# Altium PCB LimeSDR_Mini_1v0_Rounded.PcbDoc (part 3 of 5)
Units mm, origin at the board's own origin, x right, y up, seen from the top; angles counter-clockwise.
Board outline 69.3 x 52.3 mm, 8 copper layers (Top, L2, L3, L4, L5, L6, L7, Bottom), stack 1.555 mm thick; 371 components, 281 nets, 1644 pads, 778 vias.
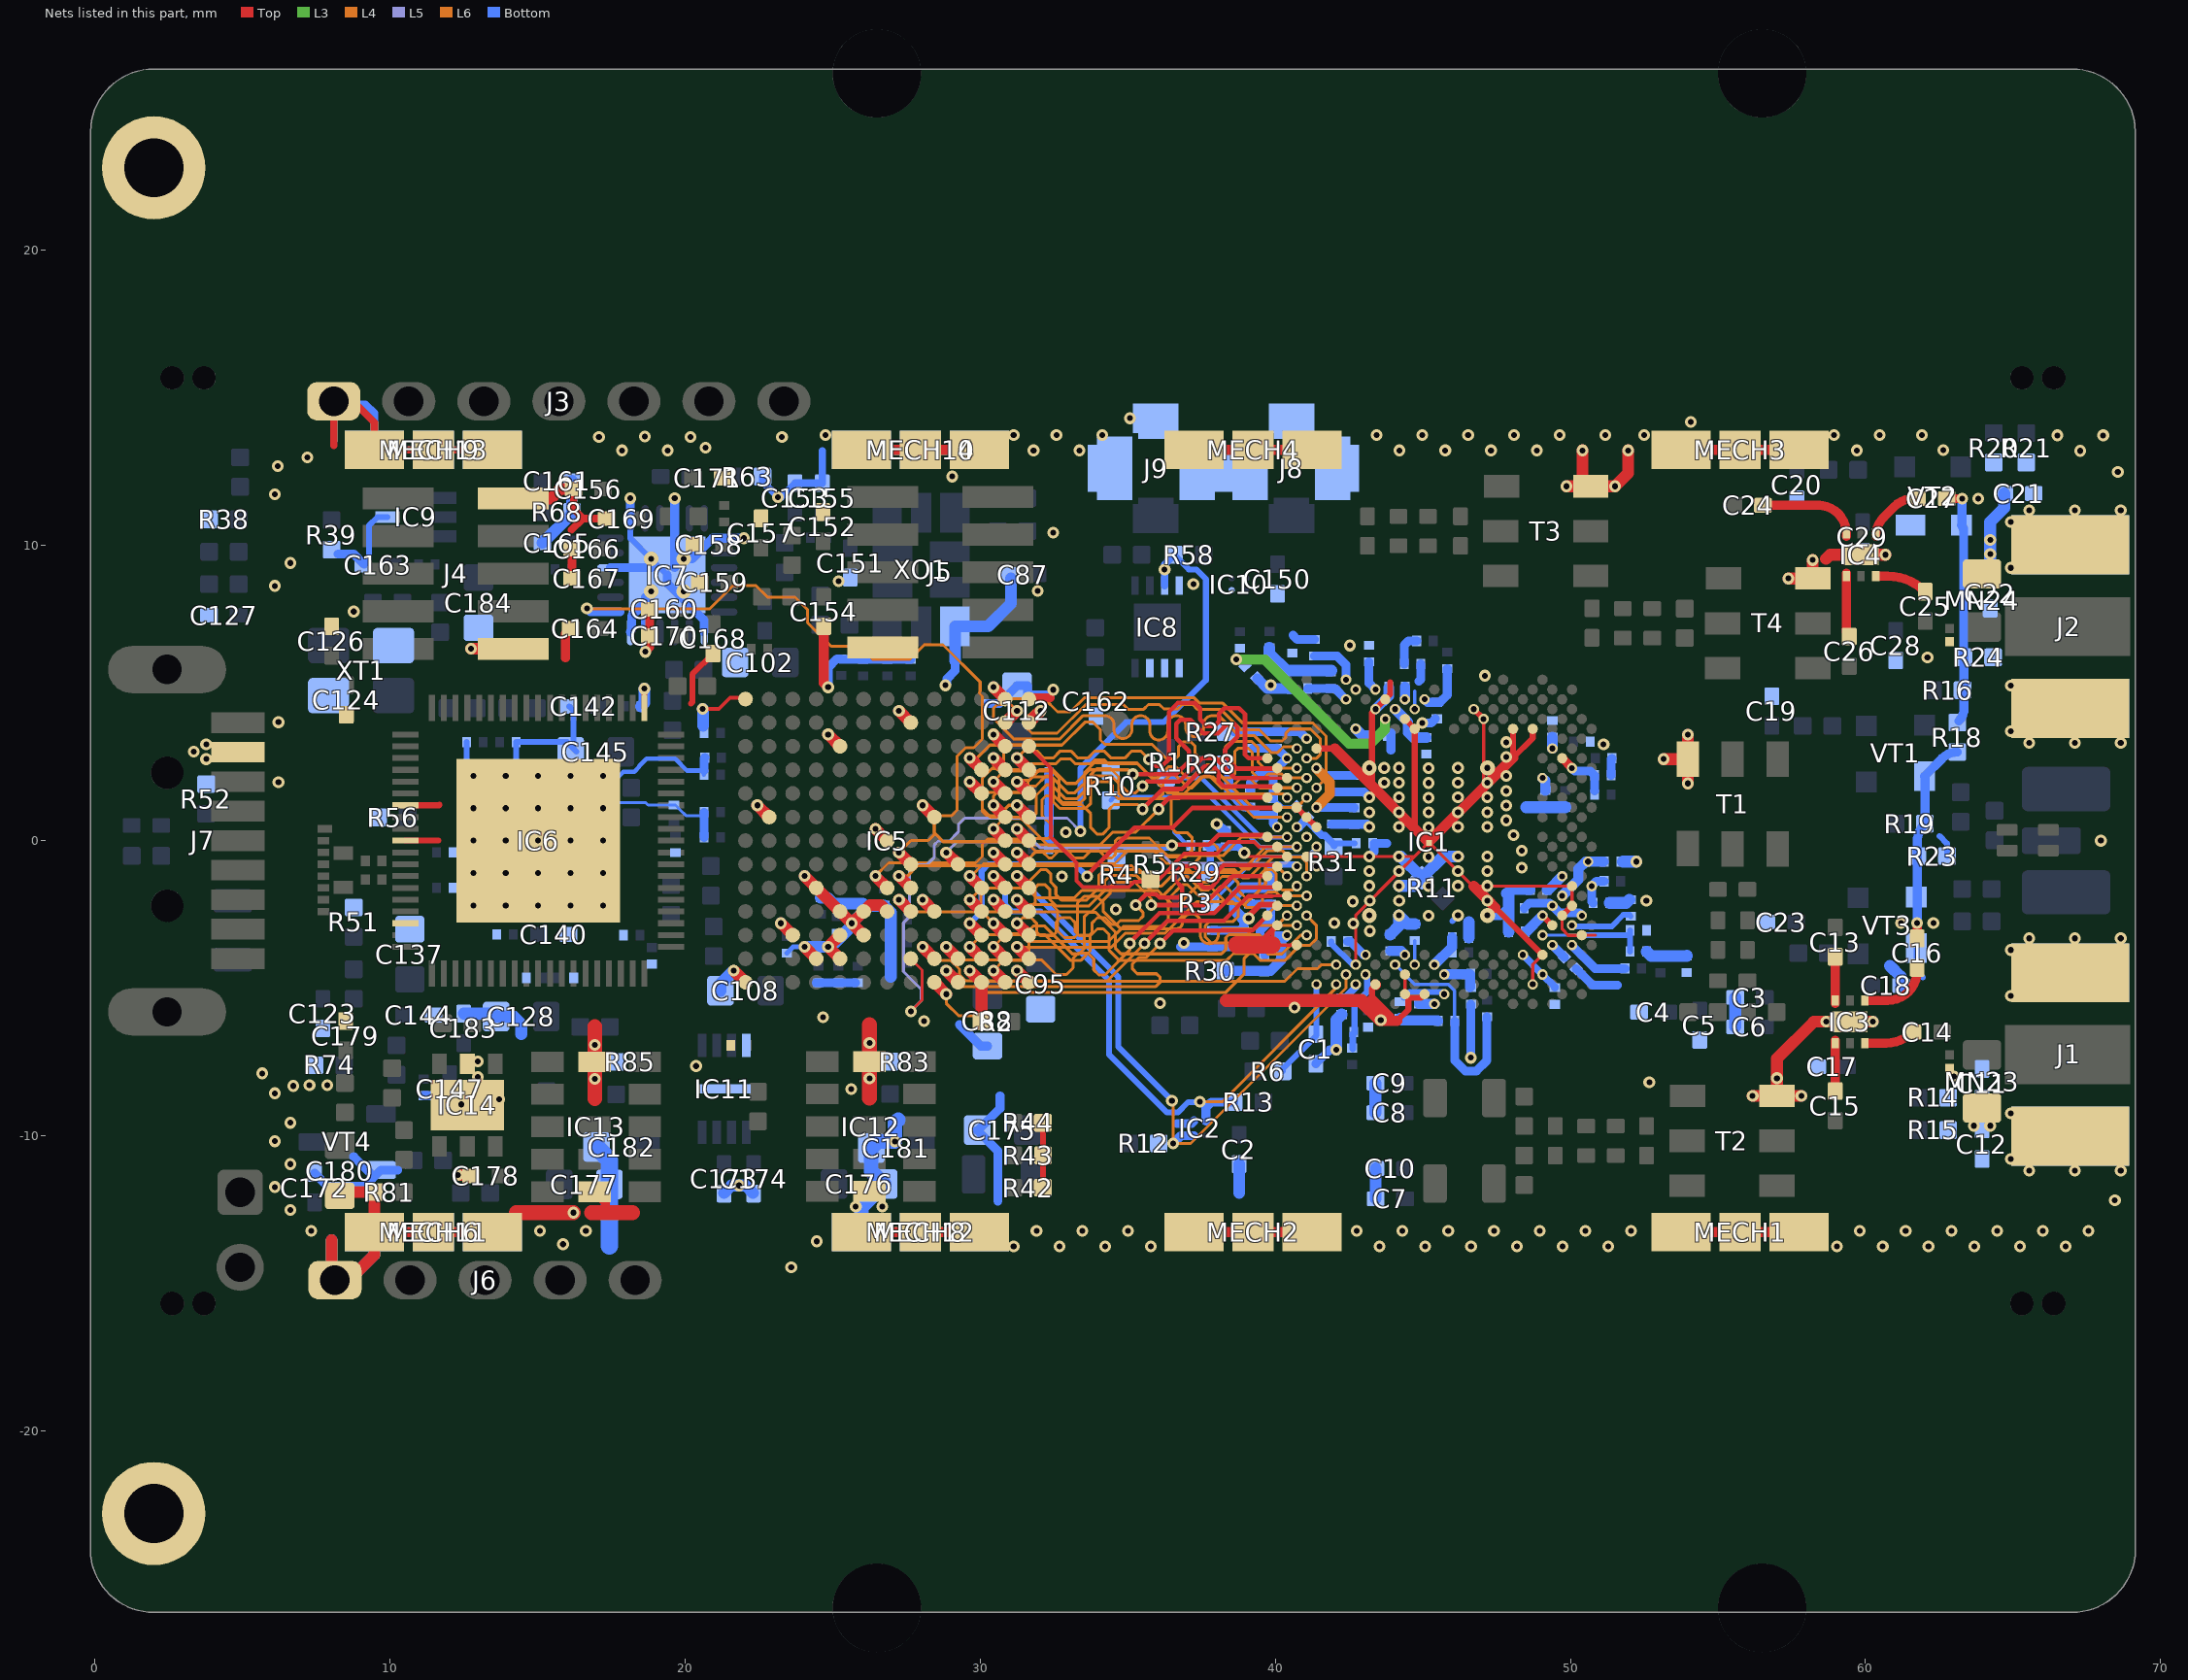
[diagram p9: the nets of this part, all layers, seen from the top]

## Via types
v1: diameter 0.4, hole 0.2, Top to Bottom, tented both sides, 544 vias
v2: diameter 0.4, hole 0.2, Top to Bottom, tented top, 113 vias
v3: diameter 0.35, hole 0.2, Top to Bottom, tented top, 87 vias
v4: diameter 0.5, hole 0.2, Top to Bottom, 25 vias
v5: diameter 0.5, hole 0.2, Top to Bottom, tented both sides, 8 vias
v6: diameter 0.35, hole 0.2, Top to Bottom, tented both sides, 1 vias

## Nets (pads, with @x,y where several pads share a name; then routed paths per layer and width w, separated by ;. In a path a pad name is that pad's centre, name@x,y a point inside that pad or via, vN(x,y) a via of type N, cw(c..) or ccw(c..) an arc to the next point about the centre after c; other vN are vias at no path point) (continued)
GND: C1.2 C2.2 C3.2 C4.1 C5.2 C6.1 C7.2 C8.2 C9.1 C10.1 C11.1 C12.2 C17.1 C18.1 C19.2 C20.2 C21.1 C22.2 C23.2 C28.1 C29.1 C30.2 C31.2 C32.2 C33.2 C34.2 C35.2 C36.2 C37.2 C38.2 C39.2 C40.2 C41.2 C42.2 C43.2 C44.2 C45.2 C46.2 C47.2 C48.2 C49.2 C50.2 C51.2 C52.2 C53.2 C54.2 C55.2 C56.2 C57.2 C58.1 C59.2 C60.2 C61.2 C62.2 C63.2 C64.2 C65.2 C66.2 C67.2 C68.2 C69.2 C70.1 C71.2 C72.2 C73.2 C74.2 C75.2 C76.2 C77.1 C78.2 C79.1 C80.2 C81.2 C82.2 C83.2 C84.2 C85.2 C86.2 C87.1 C88.1 C89.2 C90.2 C91.2 C92.2 C93.2 C94.2 C95.1 C96.2 C97.2 C98.2 C99.2 C100.2 C101.2 C102.1 C103.2 C104.2 C105.2 C106.2 C107.2 C108.1 C109.2 C110.2 C111.2 C112.1 C113.2 C114.2 C115.2 C116.2 C117.2 C118.2 C119.2 C120.2 C123.2 C124.2 C126.2 C127.2 C128.1 C129.1 C130.2 C131.1 C132.2 C133.1 C134.2 C135.1 C136.2 C137.1 C138.1 C139.2 C140.2 C141.2 C142.2 C143.2 C144.2 C145.1 C146.1 C147.2 C150.2 C151.1 C152.1 C153.1 C154.1 C155.1 C156.1 C157.1 C158.1 C159.1 C160.1 C161.1 C162.2 C163.2 C164.1 C165.1 C166.1 C167.1 C168.1 C169.1 C170.1 C171.1 C172.2 C173.1 C174.2 C175.1 C176.1 C177.1 C178.1 C179.1 C180.1 C181.1 C182.1 C183.1 C184.1 ESD1.2 ESD2.2 IC1.AA31 IC1.AF32 IC1.AG29 IC1.AJ7 IC1.AJ9 IC1.AJ19 IC1.AK12 IC1.AK20 IC1.AL13 IC1.AL23 IC1.AM22 IC1.AN25 IC1.B18 IC1.B20 IC1.C7 IC1.C23 IC1.D20 IC1.E25 IC1.F6 IC1.G31 IC1.GND IC1.H2 IC1.J33 IC1.K4 IC1.L3 IC1.N3 IC1.T30 IC1.V30 IC1.W29 IC1.Y30 IC2.B2 IC3.PAD IC4.PAD IC5.A1 IC5.A13 IC5.B8 IC5.C3 IC5.D2 IC5.D5 IC5.E2 IC5.E3 IC5.E4 IC5.E11 IC5.F3 IC5.F4 IC5.G4 IC5.G7 IC5.H12 IC5.J4 IC5.L9 IC5.M6 IC5.N1 IC5.N13 IC6.1 IC6.26 IC6.29 IC6.36 IC6.77 IC7.1 IC7.7 IC7.11 IC7.12 IC7.16 IC7.19 IC7.22 IC7.25 IC8.4 IC8.5 IC8.6 IC8.7 IC9.5 IC10.B2 IC11.4 IC11.PAD IC12.6 IC12.12 IC13.6 IC13.12 IC14.2 IC14.PAD J1.2 J2.2 J3.1 J4.2 J4.10 J5.9 J6.1 J7.4 J8.2 J9.2 MECH1.1 MECH2.1 MECH3.1 MECH4.1 MECH6.1 MECH8.1 MECH9.1 MECH10.1 MECH11.1 MECH12.1 MECH13.1 MECH14.1 NT1.2 pad.2 R10.2 R11.2 R23.1 R24.1 R38.1 R39.2 R42.1 R43.1 R44.1 R51.1 R52.1 R56.1 R63.1 R68.2 R74.1 R81.2 R83.1 R85.1 T1.3 T2.3 T3.3 T4.3 VT2.1 VT3.1 VT4.S XO1.4 XT1.2 XT1.4 | length 317.2
  Top w0.11: 39.926,-3.009 39.926,-3.283 40.179,-3.536 IC1.G31@40.731,-3.536 ; IC1.T30@41.064,-0.539 44.711,-0.539 ; v3(42.729,-4.202) 42.729,-2.521 44.204,-1.046 44.711,-0.539 ; IC1.B20@44.394,-5.201 IC1.D20@44.394,-4.535 ; 47.058,1.808 v3(47.058,4.123) ; v3(48.723,-4.868) 48.723,-4.202 IC1.F6@49.056,-3.869 ; IC1.K4@49.722,-2.537 49.722,-3.004 49.924,-3.206 50.385,-3.206 IC1.H2@50.388,-3.203 50.849,-3.203 ; IC1.L3@50.052,-2.204 IC1.N3@50.052,-1.638 ; IC1.N3@50.055,-1.538 46.725,-1.538 46.68,-1.538 45.196,-0.054 44.711,-0.539
  Top w0.12: v1(20.6,4.465) 21.15,4.465 21.528,4.843 IC5.A13@22.007,4.843
  Top w0.2: IC6.29@10.525,0 11.64,0 ; IC6.26@10.525,1.2 11.66,1.2 11.675,1.215 ; IC6.1@18.625,4.5 v1(18.625,5.15) ; 20.2,4.64 20.25,4.69 20.25,5.64 C168.1@20.95,6.34 ; R42.1@32.125,-11.76 R44.1@32.125,-9.56 ; 39.476,-3.459 39.926,-3.009 IC1.J33@40.065,-2.87 ; IC1.AA31@40.731,1.126 IC1.Y30@41.064,0.793 IC1.W29@41.397,0.46 ; IC1.AG29@41.397,3.124 42.018,3.124 ; 43.278,-5.387 43.278,-5.015 IC1.C23@43.41,-4.883 ; 43.278,1.864 43.278,4.339 v3(43.395,4.456) IC1.AM22@43.845,4.906 ; IC1.AM22@43.728,4.789 43.9,4.961 43.9,5.365 ; 44.124,-6.107 44.511,-5.72 IC1.B20@44.511,-5.318 ; IC1.B20@44.394,-5.201 IC1.B20@44.511,-5.318 ; IC1.AK20@44.394,4.123 IC1.AJ19@44.727,3.79 44.727,0.415 ; IC1.B18@45.06,-5.201 44.943,-5.318 IC1.B20@44.511,-5.318 ; v3(46.725,4.456) v3(47.058,4.123) ; 47.456,-2.269 IC1.F6@49.056,-3.869 ; IC1.AJ9@48.057,3.79 48.057,2.807 48.723,3.473 IC1.AJ7@48.723,3.79 ; IC1.K4@49.722,-2.537 IC1.L3@50.055,-2.204
  Top w0.25: 8.096,13.386 8.096,14.79 8.85,14.79 9.475,14.165 MECH9.1@9.475,13.24 MECH9.1@11.475,13.24 MECH9.1@13.475,13.24 ; 16.15,10.525 16.54,10.915 ; C156.1@16.225,11.915 16.225,11.23 16.54,10.915 ; C169.1@17.35,10.915 16.54,10.915
  Top w0.3: 15.95,6.19 15.95,7.015 C164.1@16.125,7.19 ; C167.1@16.175,8.89 C166.1@16.175,9.715 ; IC13.6@16.939,-11.895 17.3,-12.256 17.3,-12.605 ; v1(18.65,6.4) 18.8,6.55 C160.1@18.8,7.84 ; IC5.N13@31.65,4.85 32.375,4.85
  Top w0.35: MECH6.1@9.475,-13.26 MECH6.1@11.475,-13.26 MECH6.1@13.475,-13.26 ; 24.7,5.35 C154.1@24.7,7.265 ; MECH8.1@25.975,-13.26 MECH8.1@27.975,-13.26 MECH8.1@29.975,-13.26 ; MECH10.1@25.975,13.24 MECH10.1@27.975,13.24 MECH10.1@29.975,13.24 ; MECH2.1@37.25,-13.26 MECH2.1@39.25,-13.26 MECH2.1@41.25,-13.26 ; MECH4.1@37.25,13.24 MECH4.1@39.25,13.24 MECH4.1@41.25,13.24 ; 42.018,3.124 43.278,1.864 44.727,0.415 45.196,-0.054 47.058,1.808 47.204,1.954 48.057,2.807 ; 42.925,-5.414 42.925,-5.507 43.525,-6.107 44.124,-6.107 ; 43.278,-5.387 43.761,-5.871 43.875,-5.984 ; IC1.C23@43.395,-4.868 IC1.C23@43.41,-4.883 ; 46.725,-1.538 46.956,-1.769 47.206,-2.019 47.456,-2.269 ; MECH1.1@53.75,-13.26 MECH1.1@55.75,-13.26 MECH1.1@57.75,-13.26 ; MECH3.1@53.75,13.24 MECH3.1@55.75,13.24 MECH3.1@57.75,13.24
  Top w0.4: 8.025,-13.535 8.025,-14.776 J6.1@8.139,-14.89 8.62,-14.89 9.475,-14.035 MECH6.1@9.475,-13.26 R81.2@9.475,-11.91 C180.1@8.425,-11.91 ; v1(12.3,-11.335) 12.725,-11.335 C178.1@12.75,-11.36 ; v1(12.75,6.5) J4.10@14.175,6.5 ; J4.2@14.175,11.6 15.46,11.6 15.775,11.915 C156.1@16.225,11.915 ; v1(21.65,-4.4) IC5.A1@22.05,-4.8 ; v1(22.45,1.2) IC5.B8@22.85,0.8 ; v1(23.25,-2.8) IC5.C3@23.65,-3.2 ; v1(24.05,-3.6) IC5.D2@24.45,-4 ; v1(24.05,-1.2) IC5.D5@24.45,-1.6 IC5.E4@25.25,-2.4 v1(25.65,-2.8) ; v1(24.85,3.6) IC5.E11@25.25,3.2 ; IC5.E2@25.25,-4 v1(24.85,-3.6) IC5.E3@25.25,-3.2 ; IC5.F3@26.05,-3.2 v1(25.65,-2.8) ; v1(26.45,0.4) IC5.G7@26.85,0 ; IC5.G4@26.85,-2.4 26.635,-2.185 26.265,-2.185 IC5.F4@26.05,-2.4 v1(25.65,-2.8) ; v1(27.25,4.4) IC5.H12@27.65,4 ; v1(28.05,-2) IC5.J4@28.45,-2.4 ; v1(29.65,2) IC5.L9@30.05,1.6 ; v1(30.45,-0.4) IC5.M6@30.85,-0.8 ; v1(31.25,-4.4) IC5.N1@31.65,-4.8 ; v1(49.865,12.01) T3.3@50.69,12.01 v1(51.515,12.01) 51.96,12.455 v1(51.96,13.225) ; T3.3@50.415,12.01 v1@50.415,13.225 ; v1(53.155,2.765) T1.3@53.98,2.765 ; v1(53.98,1.94) T1.3@53.98,2.765 ; v1(53.98,3.59) T1.3@53.98,2.765 ; MECH3.1@55.6,13.09 MECH3.1@55.75,13.24 ; v1(56.175,-8.65) T2.3@57,-8.65 ; v1(57.39,8.885) T4.3@58.215,8.885 v1(58.215,9.51) ; v1(57.825,-8.65) T2.3@57,-8.65 ; 58.662,9.553 58.8,9.69 v1(60.675,9.69) ; IC3.PAD@59.425,-6.135 v1(58.675,-6.135) 58.25,-6.135 57,-7.385 v1(57,-8.05) T2.3@57,-8.65 ; IC3.PAD@59.5,-6.135 v1(60.25,-6.135)
  Top w0.45: 38.346,-5.414 40.65,-5.414 42.925,-5.414
  Top w0.5: 14.28,-12.605 v1(16.225,-12.605) ; 16.825,-12.605 17.3,-12.605 18.22,-12.605 ; 16.939,-8.746 v1(16.939,-8.071) IC13.12@16.939,-7.495 v1(16.939,-6.919) 16.939,-6.296 ; 26.25,-8.735 v1(26.25,-8.061) IC12.12@26.25,-7.485 26.25,-6.235
  Top w0.6: 38.7,-3.535 39.9,-3.535
  Bottom w0.1: v4(17.225,1.1) 17.59,1.465 ; 17.5,1.29 18.665,1.29 18.75,1.205 C134.2@19.625,1.205 19.675,1.205 19.825,1.055 20.03,0.85 20.645,0.85 C120.2@20.645,0.965
  Bottom w0.11: C37.2@39.926,1.416 39.974,1.416 40.261,1.129 40.703,1.129 C31.2@40.703,1.159
  Bottom w0.15: 17.375,1.965 17.538,1.965 17.913,2.34 18.282,2.34 18.45,2.508 18.45,2.53 18.695,2.775 19.665,2.775 20.065,2.375 20.645,2.375 C104.2@20.645,2.24 ; 36.579,0.294 C36.2@37.032,-0.159
  Bottom w0.17: C99.2@23.45,-3.815 23.665,-3.6 v1(24.05,-3.6)
  Bottom w0.2: C163.2@9.125,9.365 9.3,9.54 9.3,10.69 9.575,10.965 IC9.5@9.925,10.965 ; C132.2@12.595,3.34 12.595,2.045 12.65,1.99 ; 14.28,2.47 C130.2@14.28,3.34 16,3.34 C145.1@16.225,3.115 ; C142.2@16.075,4.55 16.225,4.4 C145.1@16.225,3.115 ; C145.1@16.325,3.015 C145.1@16.225,3.115 ; IC7.19@18.15,10.925 18.15,10.25 v5(18.85,9.55) IC7.25@19.4,9 ; C56.2@41.896,-3.414 41.896,-3.484 42.614,-4.202 v3(42.729,-4.202) ; 46.006,-2.719 v1(46.191,-2.534) ; VT3.1@61.725,-3.635 61.725,-4.41 61.95,-4.635 ; 62.507,0.156 62.762,-0.099 R23.1@62.762,-0.523
  Bottom w0.25: 8.096,13.536 8.096,14.79 9.175,14.79 9.475,14.49 MECH13.1@9.475,13.24 MECH13.1@11.475,13.24 MECH13.1@13.475,13.24 ; R63.1@22.625,12.34 22.625,12.165 v1(23.15,11.64) 23.25,11.64 C153.1@23.725,12.115 C155.1@24.65,12.115 ; C155.1@24.65,12.133 24.65,13.215
  Bottom w0.3: C172.2@7.45,-11.26 7.45,-11.271 7.889,-11.71 9.15,-11.71 VT4.S@9.7,-11.16 10.26,-11.16 ; R39.2@8.25,9.715 8.775,9.715 C163.2@9.125,9.365 ; 8.775,-10.71 VT4.S@9.325,-11.26 ; C146.1@11.15,-8.64 11.755,-8.64 C147.2@12.025,-8.91 ; IC7.16@17.475,9.25 IC7.25@18.85,9.25 ; IC7.12@18.15,7.075 18.2,7.125 18.2,7.615 IC7.25@18.65,8.065 ; IC7.19@18.15,10.925 v1(18.15,11.6) ; v1(18.65,6.4) IC7.11@18.65,7.075 IC7.25@18.65,8.25 ; IC7.25@19.4,9 19.4,8.716 20.65,7.466 IC7.7@20.65,7.075 ; IC7.25@19.65,9.25 IC7.22@19.65,10.925 v1(19.65,11.6) ; v5(19.95,9.55) 20.234,9.55 20.934,10.25 IC7.1@21.325,10.25 v1(22,10.25) ; C116.2@20.645,0.115 C120.2@20.645,0.965 ; C104.2@20.645,2.375 20.645,2.79 C105.2@20.67,2.815 ; C110.2@24.45,-4.815 C111.2@25.775,-4.815 ; v1(24.85,5.2) 24.85,5.865 25.151,6.166 C117.2@25.295,6.166 ; C117.2@25.27,6.141 C118.2@26.04,6.141 C114.2@26.86,6.141 27.646,6.141 C107.2@27.65,6.145 ; v1(28.825,5.265) 28.875,5.315 28.875,5.486 29.15,5.761 29.15,6.09 ; 29.3,-6.235 30.025,-6.96 C88.1@30.25,-6.96 ; C103.2@30.275,4.645 30.645,4.645 C112.1@31.25,5.25 31.6,5.25 31.6,4.94 32.236,4.94 ; 30.6,-12.21 30.6,-10.51 C175.1@29.9,-9.81 29.936,-9.81 30.675,-9.071 30.675,-8.651 ; C100.2@32.33,2.315 32.335,2.31 C91.2@32.335,-0.285 ; 36.675,-9.585 37.16,-9.585 IC2.B2@37.249,-9.496 ; v1@36.79,-3.594 38.151,-3.594 C61.2@38.926,-3.594 39.33,-3.594 39.426,-3.497 ; C62.2@39.094,-2.151 C63.2@39.806,-2.151 ; C38.2@39.151,1.691 39.151,1.961 39.509,2.319 39.926,2.319 ; C39.2@39.251,3.131 40.058,3.131 v3(40.398,2.791) 39.926,2.319 ; C33.2@39.646,-3.889 39.646,-3.717 39.426,-3.497 ; C63.2@39.851,-2.151 39.851,-2.684 39.49,-3.045 C34.2@39.49,-3.244 39.49,-3.433 39.426,-3.497 ; C37.2@39.926,1.416 39.926,2.319 ; 40.6,6.965 40.749,6.816 C72.2@41.326,6.816 ; C1.2@41.375,-7.56 41.846,-7.089 v1(42.071,-7.089) ; C64.2@41.901,0.556 43.101,0.556 v1(43.191,0.466) ; C53.2@41.901,1.656 43.001,1.656 v1(43.191,1.466) ; v1(43.191,-0.534) 43.351,-0.374 43.351,-0.089 43.781,-0.089 ; 43.921,3.066 C71.2@43.921,3.661 ; C75.2@44.371,5.986 44.371,6.625 44.514,6.768 C86.2@44.791,6.768 ; v1(44.976,3.986) 45.281,3.986 C46.2@45.426,4.131 ; v1(46.63,-7.355) C43.2@46.63,-5.54 ; v5(47.191,-2.534) 47.626,-2.534 C81.2@47.871,-2.289 ; C80.2@50.199,-4.346 50.747,-4.894 51.596,-4.894 ; C47.2@51.38,2.215 51.38,2.765 C84.2@51.405,2.79
  Bottom w0.35: MECH11.1@9.475,-13.26 MECH11.1@11.475,-13.26 MECH11.1@13.225,-13.26 ; MECH12.1@25.975,-13.26 MECH12.1@27.975,-13.26 MECH12.1@29.975,-13.26 ; MECH14.1@25.975,13.24 MECH14.1@27.975,13.24 MECH14.1@29.975,13.24 ; v1(38.015,0.568) 38.282,0.3 C35.2@38.325,0.3 ; C45.2@39.399,5.488 39.731,5.156 C49.2@40.501,5.156 ; v3(43.395,4.456) 43.845,4.905 C74.2@43.845,5.186 ; C68.2@44.225,-6.015 44.3,-6.09 C55.2@44.875,-6.09 45.5,-6.09 C42.2@45.52,-6.11 ; 47.85,-1.785 47.975,-1.66 C66.2@48.64,-1.66
  Bottom w0.4: 8.025,-13.535 8.025,-14.776 J6.1@8.139,-14.89 8.62,-14.89 9.475,-14.035 MECH11.1@9.475,-13.26 ; C183.1@12.5,-5.86 13.5,-5.86 C128.1@13.6,-5.96 14.2,-5.96 14.45,-6.21 14.45,-6.56 ; C165.1@15.175,10.09 16.175,11.09 R68.2@16.175,11.14 C161.1@16.175,12.19 ; C139.2@18.505,4.55 18.625,4.67 v1(18.625,5.15) ; v1(20.6,4.465) 20.615,4.45 20.615,3.9 ; C108.1@21.2,-5.085 21.2,-4.85 v1(21.65,-4.4) ; C173.1@21.325,-11.935 21.575,-11.685 22.05,-11.685 C174.2@22.3,-11.935 ; v1(24.05,-3.6) v1(24.85,-3.6) 24.943,-3.6 25.65,-2.893 v1(25.65,-2.8) 26.243,-2.207 26.75,-2.207 26.97,-2.427 26.97,-4.61 ; C98.2@24.6,-1.93 24.826,-1.93 25.026,-2.13 26.025,-2.13 C115.2@26.025,-2.165 ; 29.15,6.09 XO1.4@29.15,7.265 30.275,7.265 31.05,8.04 C87.1@31.05,8.888 ; 38.775,-11.935 C2.2@38.775,-10.96 ; v1(42.071,-7.089) 42.071,-6.074 C57.2@42.251,-5.894 ; C8.2@43.392,-9.218 C9.1@43.392,-8.218 ; C7.2@43.4,-12.135 C10.1@43.4,-11.11 ; C70.1@43.9,-3.175 44.191,-2.884 v1(44.191,-2.534) 44.486,-2.829 C69.2@44.727,-2.829 ; v1(44.191,-1.534) 44.691,-1.534 R11.2@44.971,-1.254 ; v1(44.191,-0.534) 44.252,-0.534 R11.2@44.971,-1.254 ; v1(46.191,-0.534) 45.691,-0.534 R11.2@44.971,-1.254 ; C44.2@46.555,-3.285 46.555,-2.755 ; 47.85,-1.785 47.915,-1.85 C79.1@47.915,-3.085 ; 48.505,1.135 C77.1@49.15,1.135 C85.2@49.825,1.135 ; C48.2@51.331,-2.114 51.331,-2.107 51.89,-2.107 C78.2@52,-1.997 ; C58.1@51.785,-0.71 v1(52.235,-0.71) ; C6.1@55.585,-6.31 C3.2@55.585,-5.31 ; 60.825,-4.235 61.2,-4.61 C18.1@61.2,-4.91
  Bottom w0.5: MECH12.1@25.975,-13.26 25.975,-12.41 C176.1@26.75,-11.635 26.311,-11.196 C181.1@26.311,-10.42 26.536,-10.195 v1(27.111,-10.195) 27.111,-9.574 27.225,-9.46
  Bottom w0.6: C182.1@17,-10.38 17.439,-10.819 C177.1@17.439,-11.645 17.439,-13.726
  other v1: 23.6,-14.46 31.135,-13.75 32.685,-13.75 34.235,-13.75 35.785,-13.75 43.535,-13.75 45.085,-13.75 46.635,-13.75 48.185,-13.75 49.735,-13.75 51.285,-13.75 59.035,-13.75 60.585,-13.75 62.135,-13.75 63.685,-13.75 65.235,-13.75 66.785,-13.75 15.865,-13.675 24.46,-13.575 7.34,-13.225 15.09,-13.225 16.64,-13.225 31.91,-13.225 33.46,-13.225 35.01,-13.225 42.76,-13.225 44.31,-13.225 45.86,-13.225 47.41,-13.225 48.96,-13.225 50.51,-13.225 52.06,-13.225 59.81,-13.225 61.36,-13.225 62.91,-13.225 64.46,-13.225 66.01,-13.225 67.56,-13.225 6.625,-12.51 25.786,-12.395 26.686,-12.395 68.45,-12.185 6.1,-11.735 21.825,-11.685 65.55,-11.185 67.1,-11.185 68.65,-11.185 6.625,-10.96 64.925,-10.79 6.1,-10.185 6.625,-9.56 64.925,-9.24 12.425,-8.935 13.7,-8.76 6.1,-8.56 25.636,-8.42 6.725,-8.31 7.275,-8.285 7.875,-8.285 52.675,-8.185 12.975,-8.01 63,-7.985 5.675,-7.885 20.375,-7.635 12.975,-7.485 26.25,-6.86 28.1,-6.11 43.575,-6.082 24.675,-5.985 40.65,-5.657 36.1,-5.507 64.925,-5.255 64.925,-3.705 36.9,-3.46 65.55,-3.31 67.1,-3.31 68.65,-3.31 43.2,-3.06 42.65,-2.81 42,-2.785 61.2,-2.785 62.3,-2.785 45.191,-2.544 34.6,-2.335 42.625,-2.06 43.2,-2.035 44.2,-2.035 47.191,-2.034 52.575,-2.032 43.191,-1.534 45.191,-1.544 46.191,-1.534 47.191,-1.534 32.775,-1.21 43.191,-1.034 44.191,-1.034 46.191,-1.034 47.191,-1.034 48.35,-0.91 45.191,-0.544 47.191,-0.534 48.35,-0.335 67.975,0 48.075,0.19 32.9,0.29 45.191,0.456 44.191,0.466 46.191,0.466 47.191,0.466 47.825,0.69 45.191,0.956 43.191,0.966 44.191,0.966 46.191,0.966 47.191,0.966 47.825,1.19 44.191,1.466 45.191,1.456 46.191,1.466 47.191,1.466 47.825,1.69 43.691,1.966 44.191,1.966 45.191,1.956 46.191,1.966 47.191,1.966 6.225,1.985 47.825,2.19 45.191,2.456 43.691,2.466 44.191,2.466 46.191,2.466 3.775,2.765 47.826,2.836 3.35,3.015 3.775,3.265 51.125,3.265 65.55,3.315 67.1,3.315 68.65,3.315 47.826,3.336 64.925,3.71 6.225,4.015 32.475,5.115 39.85,5.268 64.925,5.26 47.1,5.59 62.1,6.215 42.525,6.615 8.775,7.765 31.95,8.465 6.1,8.635 37.225,8.69 25.2,8.79 64.925,9.245 6.625,9.41 32.475,10.44 64.925,10.795 65.55,11.19 67.1,11.19 68.65,11.19 63.825,11.59 6.1,11.735 29.05,12.34 68.55,12.49 6.2,12.69 7.2,12.99 17.86,13.225 19.41,13.225 31.81,13.225 33.36,13.225 44.21,13.225 45.76,13.225 47.31,13.225 48.86,13.225 50.41,13.225 59.71,13.225 67.28,13.21 62.63,13.235 20.7,13.315 17.085,13.675 20.185,13.675 23.285,13.675 18.635,13.7 52.5,13.74 66.505,13.735 68.055,13.735 24.76,13.75 31.135,13.75 32.585,13.75 34.135,13.75 43.435,13.75 44.985,13.75 46.535,13.75 48.085,13.75 49.635,13.75 51.185,13.75 58.935,13.75 60.485,13.75 61.915,13.75 54.075,14.19 35.075,14.315
  other v3: 41.064,0.127 42.729,5.122
  other v4: 12.825,-2.2 13.925,-2.2 15.025,-2.2 16.125,-2.2 17.225,-2.2 12.825,-1.1 13.925,-1.1 15.025,-1.1 16.125,-1.1 17.225,-1.1 12.825,0 13.925,0 15.025,0 16.125,0 17.225,0 12.825,1.1 13.925,1.1 15.025,1.1 16.125,1.1 12.825,2.2 13.925,2.2 15.025,2.2 16.125,2.2 17.225,2.2
  other v5: 43.191,-2.534 43.191,2.466 47.191,2.466 18.85,8.45 19.95,8.45
LM75_OS: IC5.H2 IC8.3 R58.1 | length 28.1
  Top w0.1: v1@27.624,-5.785 v1(27.65,-5.785) 28.035,-5.401 28.035,-4.385 IC5.H2@27.65,-4
  L5 w0.1: v1(27.65,-5.785) 28,-5.435 28,-5.035 27.4,-4.435 27.4,-2.785 27.6,-2.585 27.6,-1.035 27.825,-0.81 28.2,-0.81 28.45,-0.56 28.45,-0.135 28.575,-0.01 28.957,-0.01 29.262,0.295 29.262,0.552 29.475,0.765 32.95,0.765 v1(33.4,0.315)
  Bottom w0.2: v1(33.4,0.315) 33.4,2.465 34.95,4.015 36.225,4.015 37.65,5.44 37.65,8.865 37.325,9.19 37.075,9.19 R58.1@36.575,9.69
  Bottom w0.25: IC8.3@36.25,8.64 36.25,9.365 R58.1@36.575,9.69
  other v1: 36.25,9.19
LMK_CLK: IC5.H6 IC7.13 | length 25.2
  Top w0.4: v2(27.25,-0.4) IC5.H6@27.65,-0.8
  L6 w0.1: v1@16.675,7.85 20.827,7.85 21.617,8.64 22.408,8.64 22.791,8.257 23.725,8.257 24.15,7.832 24.15,7.39 24.95,6.59 25.925,6.59 26.375,6.14 27.608,6.14 28.108,6.64 28.742,6.64 30,5.382 30,5.055 29.975,5.03 29.975,4.99 30.075,4.89 30.075,3.44 29.785,3.15 29.505,3.15 29.225,2.87 29.225,1.04 29.025,0.84 28.6,0.84 28.45,0.69 28.45,0.215 28.235,0 27.65,0 v2(27.25,-0.4)
  Bottom w0.3: v1(16.675,7.875) 16.8,7.75 IC7.13@17.475,7.75 IC7.13@17.8,7.75
LMS_CORE_LDO_EN: IC1.U33 IC5.N11 R5.1 | length 12.8
  Top w0.11: 39.451,-0.206 IC1.U33@40.065,-0.206
  Top w0.13: IC5.N11@31.65,3.2 32.393,2.457 32.393,0.122 33.26,-0.745 33.26,-1.361 33.474,-1.575 35.035,-1.575 35.225,-1.385 35.975,-1.385 36.925,-0.435 38.03,-0.435 38.416,-0.049 39.294,-0.049 39.451,-0.206
LMS_DIQ1_D0: IC1.AG31 IC5.M12 | length 16.4
  Top w0.4: IC5.M12@30.85,4 v2(31.25,4.4)
  L6 w0.1: v2(31.25,4.4) 31.035,4.615 30.575,4.615 30.45,4.49 30.45,4.14 31.15,3.44 32.692,3.44 33.492,4.24 34.075,4.24 34.227,4.24 cw(c34.227,3.936) 34.531,3.936 34.531,3.769 ccw(c34.835,3.769) 34.835,3.465 ccw(c34.835,3.769) 35.139,3.769 35.139,3.936 cw(c35.443,3.936) 35.443,4.24 cw(c35.443,3.936) 35.747,3.936 35.747,3.715 ccw(c36.051,3.715) 36.051,3.411 ccw(c36.051,3.715) 36.355,3.715 36.355,3.936 cw(c36.659,3.936) 36.659,4.24 cw(c36.659,3.936) 36.963,3.936 36.963,3.83 ccw(c37.267,3.83) 37.267,3.526 ccw(c37.267,3.83) 37.571,3.83 37.571,3.936 cw(c37.875,3.936) 37.875,4.24 38.075,4.24 38.75,3.565 39.283,3.565 39.858,2.99 40.085,2.99 40.275,3.18 40.675,3.18 v3(40.731,3.124)
LMS_DIQ1_D1: IC1.AF30 IC5.N12 | length 14.1
  Top w0.4: IC5.N12@31.65,4 v2(32.05,4.4)
  L6 w0.1: v2(32.05,4.4) 31.81,4.4 31.55,4.14 31.55,3.84 31.75,3.64 32.609,3.64 33.584,4.615 34.854,4.615 35.013,4.456 35.541,4.456 35.7,4.615 36.075,4.615 36.225,4.465 36.7,4.465 36.85,4.615 37.2,4.615 37.359,4.456 38.141,4.456 38.833,3.765 39.45,3.765 39.835,3.38 40.24,3.38 40.35,3.49 40.35,3.632 40.5,3.782 41.199,3.782 41.522,3.459 41.522,2.912 41.401,2.791 v3(41.064,2.791)
LMS_DIQ1_D2: IC1.AF34 IC5.N10 | length 14.2
  Top w0.15: v1(35.725,2.75) 35.935,2.54 36.175,2.54 36.4,2.765 36.4,4.365 36.7,4.665 37.275,4.665 37.45,4.49 37.45,4.115 37.675,3.89 37.95,3.89 38.1,4.04 38.1,4.315 38.275,4.49 38.775,4.49 38.975,4.29 38.975,2.916 39.1,2.791 IC1.AF34@39.732,2.791
  Top w0.4: v2(31.25,2.8) IC5.N10@31.65,2.4
  L6 w0.1: v2(31.25,2.8) 31.49,3.04 31.925,3.04 32.165,2.8 32.475,2.8 32.715,3.04 33.075,3.04 33.315,2.8 33.65,2.8 33.89,3.04 34.2,3.04 34.44,2.8 34.9,2.8 35.14,3.04 35.435,3.04 v1(35.725,2.75)
LMS_DIQ1_D3: IC1.AE31 IC5.L10 | length 14.7
  Top w0.4: v2(29.65,2.8) IC5.L10@30.05,2.4
  L6 w0.1: v2(29.65,2.8) 29.885,2.8 30.325,3.24 32.775,3.24 33.55,4.015 33.825,4.015 34.075,3.765 34.075,3.415 34.225,3.265 35.825,3.265 36.325,2.765 36.6,2.765 36.725,2.89 36.725,3.19 36.875,3.34 37.15,3.34 37.275,3.215 37.275,2.965 37.475,2.765 38.125,2.765 38.325,2.965 38.325,3.19 38.5,3.365 39.2,3.365 39.425,3.14 39.425,2.658 39.625,2.458 v3(40.731,2.458)
LMS_DIQ1_D4: IC1.AD30 IC5.M10 | length 14.5
  Top w0.4: v2(30.45,2.8) IC5.M10@30.85,2.4
  L6 w0.1: v2(30.45,2.8) 30.45,2.54 30.575,2.415 31.5,2.415 31.685,2.6 32.558,2.6 32.723,2.765 33.067,2.765 33.232,2.6 33.733,2.6 33.873,2.74 34.217,2.74 34.357,2.6 35.34,2.6 35.815,2.125 36.01,2.125 36.4,2.515 36.625,2.515 37.015,2.125 37.235,2.125 37.675,2.565 37.8,2.565 38.24,2.125 38.485,2.125 38.625,2.265 38.625,3.015 38.75,3.14 39.075,3.14 39.225,2.99 39.225,2.315 39.415,2.125 39.625,2.125 39.758,2.258 40.217,2.258 40.35,2.125 v3(41.064,2.125)
LMS_DIQ1_D5: IC1.AC29 IC5.M13 | length 14.8
  Top w0.4: v2(30.45,5.2) IC5.M13@30.85,4.8
  L6 w0.1: v2(30.45,5.2) 30.835,4.815 32.175,4.815 32.625,4.365 33.051,4.365 33.526,4.84 37.258,4.84 37.441,4.656 38.224,4.656 38.899,3.982 41.281,3.982 41.722,3.541 41.722,2.117 v3(41.397,1.792)
LMS_DIQ1_D6: IC1.AE33 IC5.N9 | length 14.2
  Top w0.15: v1(35.175,2.25) 36.635,2.25 37.075,2.69 37.075,3.04 36.65,3.465 36.65,3.965 36.775,4.09 37.121,4.09 37.571,3.64 38.054,3.64 38.379,3.965 38.6,3.965 38.725,3.84 38.725,3.515 38.3,3.09 38.3,2.84 38.699,2.441 40.048,2.441 IC1.AE33@40.065,2.458
  Top w0.4: v2(31.25,2) IC5.N9@31.65,1.6
  L6 w0.1: v2(31.25,2) 31.3,2.05 31.66,2.05 32.01,2.4 32.473,2.4 32.933,1.94 33.242,1.94 33.702,2.4 35.025,2.4 v1(35.175,2.25)
LMS_DIQ1_D7: IC1.AD32 IC5.N8 | length 14.5
  Top w0.11: 39.79,2.125 IC1.AD32@40.398,2.125
  Top w0.15: v1(35.5,1.85) 35.65,2 36.739,2 37.529,2.79 37.975,2.79 38.64,2.125 39.79,2.125
  Top w0.4: v2(31.25,1.2) IC5.N8@31.65,0.8
  L6 w0.1: v2(31.25,1.2) 30.967,1.2 30.607,0.84 30.225,0.84 30.075,0.99 30.075,1.49 30.225,1.64 31.425,1.64 31.635,1.85 31.885,1.85 32.225,2.19 32.4,2.19 32.965,1.625 33.21,1.625 33.775,2.19 34.45,2.19 35.015,1.625 35.275,1.625 v1(35.5,1.85)
LMS_DIQ1_D8: IC1.AC31 IC5.M7 | length 14
  Top w0.4: v2(30.45,0.4) IC5.M7@30.85,0
  L6 w0.1: v2(30.45,0.4) 30.8,0.75 31.735,0.75 31.9,0.915 31.9,1.54 32.25,1.89 32.417,1.89 32.882,1.425 33.293,1.425 33.858,1.99 34.367,1.99 34.475,1.882 34.475,1.615 34.665,1.425 36.035,1.425 36.2,1.59 36.2,1.99 36.45,2.24 36.602,2.24 37.05,1.792 37.185,1.792 37.579,2.186 37.781,2.186 38.175,1.792 38.502,1.792 38.825,2.115 39.142,2.115 39.465,1.792 v3(40.731,1.792)
LMS_DIQ1_D9: IC1.AC33 IC5.N7 | length 14
  Top w0.15: v1(35.5,1.068) 36.182,1.75 36.842,1.75 37.607,2.515 37.896,2.515 38.086,2.326 38.086,2.004 38.256,1.834 40.023,1.834 IC1.AC33@40.065,1.792
  Top w0.4: v2(31.25,0.4) IC5.N7@31.65,0
  L6 w0.1: v2(31.25,0.4) 31.585,0.065 32.3,0.065 32.425,0.19 32.425,0.515 32.1,0.84 32.1,1.39 32.23,1.52 32.505,1.52 32.799,1.225 33.44,1.225 33.75,0.915 33.75,0.44 33.975,0.215 34.142,0.215 34.375,0.448 34.375,1.065 34.535,1.225 35.343,1.225 v1(35.5,1.068)
LMS_DIQ1_D10: IC1.AB30 IC5.M9 | length 14.7
  Top w0.4: v2(30.45,2) IC5.M9@30.85,1.6
  L4 w0.1: v2(30.45,2) 30.815,2.365 32.433,2.365 32.675,2.123 32.675,1.415 32.8,1.29 33.4,1.29 33.55,1.44 33.55,2.323 33.867,2.64 35.325,2.64 36.347,1.618 36.653,1.618 37.4,2.365 37.983,2.365 39.23,1.118 40.723,1.118 v3(41.064,1.459)
LMS_DIQ1_D11: IC1.AB32 IC5.N6 | length 14.4
  Top w0.4: v2(31.25,-0.4) IC5.N6@31.65,-0.8
  L6 w0.1: v2(31.25,-0.4) 31.435,-0.585 31.675,-0.585 31.875,-0.385 32.125,-0.385 32.325,-0.585 32.425,-0.585 32.675,-0.335 32.95,-0.335 33.2,-0.585 33.5,-0.585 33.75,-0.335 34.025,-0.335 34.275,-0.585 34.467,-0.585 34.575,-0.477 34.575,-0.01 34.675,0.09 35.733,0.09 36.383,-0.56 36.95,-0.56 37.175,-0.335 37.175,0.115 37.025,0.265 36.65,0.265 36.475,0.44 36.475,1.465 36.6,1.59 40.267,1.59 v3(40.398,1.459)
LMS_DIQ2_D0: IC1.H30 IC5.M2 | length 15.2
  Top w0.4: v2(30.45,-3.6) IC5.M2@30.85,-4
  L4 w0.1: v2(30.45,-3.6) 30.89,-3.16 31.542,-3.16 31.817,-2.885 32.175,-2.885 33.125,-3.835 33.35,-3.835 33.525,-3.66 33.525,-2.585 33.675,-2.435 33.922,-2.435 34.575,-3.088 34.575,-3.635 34.775,-3.835 38.175,-3.835 38.325,-3.685 38.325,-3.282 38.425,-3.182 39.472,-3.182 39.613,-3.323 39.613,-3.698 39.75,-3.835 40.226,-3.835 40.858,-3.203 v3(41.064,-3.203)
LMS_DIQ2_D1: IC1.J31 IC5.M4 | length 15.3
  Top w0.4: v2(30.45,-2) IC5.M4@30.85,-2.4
  L4 w0.1: v2(30.45,-2) 30.45,-2.235 30.625,-2.41 31.45,-2.41 31.7,-2.16 32.425,-2.16 32.625,-2.36 32.625,-3.052 32.858,-3.285 33.2,-3.285 33.3,-3.185 33.3,-2.11 33.525,-1.885 33.95,-1.885 34.175,-2.11 34.175,-2.405 34.752,-2.982 36.55,-2.982 36.65,-2.982 ccw(c36.65,-2.778) 36.854,-2.778 cw(c37.158,-2.778) 37.158,-2.474 cw(c37.158,-2.778) 37.462,-2.778 37.462,-2.982 37.462,-3.186 ccw(c37.766,-3.186) 37.766,-3.49 ccw(c37.766,-3.186) 38.07,-3.186 cw(c38.274,-3.186) 38.274,-2.982 38.65,-2.982 39.328,-2.982 39.44,-2.87 v3(40.731,-2.87)
LMS_DIQ2_D2: IC1.K30 IC5.M1 | length 15.6
  Top w0.4: v2(30.45,-4.4) IC5.M1@30.85,-4.8
  L4 w0.1: v2(30.45,-4.4) 30.8,-4.05 31.51,-4.05 31.65,-3.91 31.65,-3.335 31.8,-3.185 32.192,-3.185 33.057,-4.05 33.418,-4.05 33.725,-3.743 33.725,-3.235 33.975,-2.985 34.175,-2.985 34.375,-3.185 34.375,-3.718 34.707,-4.05 38.36,-4.05 38.584,-3.826 39.259,-3.826 39.482,-4.05 40.335,-4.05 40.841,-3.544 41.183,-3.544 41.389,-3.338 41.389,-2.862 v3(41.064,-2.537)
LMS_DIQ2_D3: IC1.K32 IC5.J1 | length 14.6
  Top w0.4: IC5.J1@28.45,-4.8 v2(28.85,-5.2)
  L6 w0.1: v2(28.85,-5.2) 28.85,-5.51 29.275,-5.935 29.8,-5.935 29.95,-5.785 29.95,-5.31 30.11,-5.15 38.31,-5.15 38.95,-4.51 38.95,-3.985 v3(40.398,-2.537)
LMS_DIQ2_D4: IC1.L31 IC5.N2 | length 14.4
  Top w0.4: v2(31.25,-3.6) IC5.N2@31.65,-4
  L6 w0.1: v2(31.25,-3.6) 31.26,-3.61 34.447,-3.61 34.925,-3.132 36.278,-3.132 37.339,-2.071 38.561,-2.071 38.75,-2.26 38.75,-2.56 38.575,-2.735 37.775,-2.735 37.625,-2.885 37.625,-3.26 37.825,-3.46 38.775,-3.46 40.031,-2.204 v3(40.731,-2.204)
LMS_DIQ2_D5: IC1.K34 IC5.K1 | length 14.9
  Top w0.15: v1(36.1,-3.482) 36.544,-3.039 39.23,-3.039 IC1.K34@39.732,-2.537
  Top w0.4: v2(28.85,-4.4) IC5.K1@29.25,-4.8
  L6 w0.1: v2(28.85,-4.4) 28.85,-4.61 29.19,-4.95 35.935,-4.95 36.1,-4.785 36.1,-4.635 35.975,-4.51 35.325,-4.51 35.165,-4.35 35.165,-4.175 35.383,-3.957 35.625,-3.957 v1(36.1,-3.482)
LMS_DIQ2_D6: IC1.M30 IC5.L2 | length 14.5
  Top w0.4: v2(29.65,-3.6) IC5.L2@30.05,-4
  L6 w0.1: v2(29.65,-3.6) 30.065,-3.185 31.375,-3.185 31.6,-3.41 34.35,-3.41 34.85,-2.91 36.2,-2.91 36.375,-2.735 36.375,-1.968 36.858,-1.485 37.017,-1.485 37.403,-1.871 37.822,-1.871 38.129,-1.564 38.337,-1.564 39.033,-2.26 39.425,-2.26 39.575,-2.11 39.575,-1.91 39.75,-1.735 40.017,-1.735 40.153,-1.871 v3(41.064,-1.871)
LMS_DIQ2_D7: IC1.M32 IC5.J2 | length 14.7
  Top w0.11: 39.894,-1.871 IC1.M32@40.398,-1.871
  Top w0.15: v1(35.575,-3.482) 35.725,-3.332 35.725,-3.327 36.342,-2.71 38.254,-2.71 39.093,-1.871 39.894,-1.871
  Top w0.4: v2(28.05,-3.6) IC5.J2@28.45,-4
  L6 w0.1: v2(28.05,-3.6) 28.5,-4.05 28.995,-4.05 29.3,-4.355 29.3,-4.545 29.505,-4.75 34.307,-4.75 v1(35.575,-3.482)
LMS_DIQ2_D8: IC1.N31 IC5.N4 | length 14.5
  Top w0.4: v2(31.25,-2) IC5.N4@31.65,-2.4
  L6 w0.1: v2(31.25,-2) 31.46,-2.21 31.75,-2.21 31.875,-2.085 31.875,-1.585 31.975,-1.485 32.192,-1.485 32.367,-1.66 32.367,-2.002 32.575,-2.21 33.692,-2.21 34.225,-1.677 34.225,-1.36 34.4,-1.185 35.298,-1.185 35.986,-1.874 36.186,-1.874 36.85,-1.21 37.025,-1.21 37.486,-1.671 37.739,-1.671 38.2,-1.21 38.525,-1.21 38.75,-1.435 38.75,-1.694 39.041,-1.985 39.17,-1.985 39.475,-1.68 39.475,-1.168 39.658,-0.985 39.895,-0.985 40.023,-1.112 40.023,-1.458 40.236,-1.671 40.598,-1.671 v3(40.731,-1.538)
LMS_DIQ2_D9: IC1.N33 IC5.K2 | length 14.6
  Top w0.15: v1@35.057,-3.47 36.067,-2.46 37.925,-2.46 38.805,-1.58 40.065,-1.58 IC1.N33@40.065,-1.538
  Top w0.4: v2(28.85,-3.6) IC5.K2@29.25,-4
  L6 w0.1: v2(28.85,-3.6) 29.285,-4.035 32.075,-4.035 32.575,-4.535 32.925,-4.535 33.15,-4.31 33.15,-3.985 33.325,-3.81 33.65,-3.81 33.85,-4.01 33.85,-4.375 34.025,-4.55 34.225,-4.55 35.07,-3.705 v1(35.07,-3.482)
LMS_DIQ2_D10: IC1.P30 IC5.L5 | length 14.4
  Top w0.4: v2(29.65,-1.2) IC5.L5@30.05,-1.6
  L6 w0.1: v2(29.65,-1.2) 29.693,-1.2 30.108,-0.785 34.55,-0.785 35.05,-0.285 35.825,-0.285 36.304,-0.764 37.246,-0.764 37.45,-0.56 37.45,-0.235 37.575,-0.11 37.925,-0.11 38.05,-0.235 38.05,-0.535 38.279,-0.764 38.686,-0.764 38.879,-0.956 39.121,-0.956 39.742,-0.335 40.238,-0.335 40.45,-0.547 40.866,-0.547 41.064,-0.745 v3(41.064,-1.205)
LMS_DIQ2_D11: IC1.P32 IC5.L4 | length 14.4
  Top w0.4: v2(29.65,-2) IC5.L4@30.05,-2.4
  L6 w0.1: v2(29.65,-2) 30.04,-1.61 31.425,-1.61 32.05,-0.985 32.25,-0.985 32.4,-1.135 32.4,-1.41 32.567,-1.577 32.567,-1.827 32.75,-2.01 33.609,-2.01 34.025,-1.594 34.025,-1.16 34.2,-0.985 35.4,-0.985 35.95,-1.535 36.15,-1.535 36.7,-0.985 37.083,-0.985 37.508,-1.41 37.717,-1.41 38.138,-0.989 38.629,-0.989 38.896,-1.256 39.104,-1.256 39.575,-0.785 39.978,-0.785 v3(40.398,-1.205)
LMS_ENABLE_IQSEL1: IC1.Y32 IC5.M8 | length 14.9
  Top w0.4: v2(30.45,1.2) IC5.M8@30.85,0.8
  L4 w0.1: v2(30.45,1.2) 30.45,1.515 30.575,1.64 31.475,1.64 31.625,1.79 31.625,2.015 31.775,2.165 32.35,2.165 32.475,2.04 32.475,1.315 32.7,1.09 33.575,1.09 33.75,1.265 33.75,2.24 33.95,2.44 34.425,2.44 34.7,2.165 34.7,1.59 34.872,1.418 35.905,1.418 36.736,1.418 37.483,2.165 37.9,2.165 39.272,0.793 v3(40.398,0.793)
LMS_ENABLE_IQSEL2: IC1.R33 IC5.N3 | length 14.6
  Top w0.15: v1@35.275,-2.16 35.628,-1.807 35.955,-1.807 36.08,-1.932 36.728,-1.932 36.85,-1.81 36.85,-1.585 36.575,-1.31 36.575,-1.124 36.839,-0.86 37.25,-0.86 37.4,-1.01 37.4,-1.41 37.538,-1.548 37.586,-1.596 37.811,-1.596 38.05,-1.356 38.05,-1.035 38.255,-0.83 40.023,-0.83 IC1.R33@40.065,-0.872
  Top w0.4: v2(31.25,-2.8) IC5.N3@31.65,-3.2
  L6 w0.1: v2(31.25,-2.8) 31.44,-2.61 31.725,-2.61 31.912,-2.798 31.912,-3.097 32.025,-3.21 32.475,-3.21 32.575,-3.11 32.575,-2.76 32.725,-2.61 33.05,-2.61 33.225,-2.785 33.225,-3.085 33.35,-3.21 33.7,-3.21 33.787,-3.123 33.787,-2.798 33.975,-2.61 34.225,-2.61 34.459,-2.844 34.614,-2.844 34.747,-2.71 35.375,-2.71 35.516,-2.569 35.516,-2.424 v1(35.275,-2.182)
LMS_FCLK1: IC1.AA33 IC5.L3 | length 13.8
  Top w0.15: v1(33.625,-1.21) 33.625,-1.173 35.238,0.44 36.525,0.44 37.194,1.109 40.065,1.109 IC1.AA33@40.065,1.126
  Top w0.4: v2(29.65,-2.8) IC5.L3@30.05,-3.2
  Bottom w0.2: v2(29.65,-2.8) 30.05,-2.4 30.05,-1.034 30.284,-0.8 30.375,-0.8 33.215,-0.8 v1(33.625,-1.21)
LMS_FCLK2: IC1.R29 IC5.M3 | length 15.3
  Top w0.4: v2(30.45,-2.8) IC5.M3@30.85,-3.2
  L4 w0.1: v2(30.45,-2.8) 30.025,-2.375 30.025,-1.86 30.275,-1.61 31.575,-1.61 31.9,-1.935 33.192,-1.935 33.442,-1.685 36.025,-1.685 36.5,-2.16 36.725,-2.16 37.35,-1.535 37.775,-1.535 38.375,-2.135 39,-2.135 39.675,-1.46 39.675,-0.81 39.938,-0.547 41.072,-0.547 v3(41.397,-0.872)
LMS_I2C_SCL: IC1.C27 IC2.A2 IC5.M5 R13.2 | length 20.7
  Top w0.4: v2(30.45,-1.2) IC5.M5@30.85,-1.6
  L4 w0.1: v1(37.447,-8.85) 38.202,-8.85 42.063,-4.989 v3(42.063,-4.868)
  Bottom w0.2: v2(30.45,-1.2) 30.85,-1.6 30.85,-2.166 31.084,-2.4 32.04,-2.4 34.375,-4.735 34.375,-7.251 36.334,-9.21 36.7,-9.21 37.05,-8.86 v1@37.475,-8.86
  Bottom w0.3: IC2.A2@37.649,-9.496 37.649,-9.052 37.841,-8.86 R13.2@38.6,-8.86
LMS_I2C_SDA: IC1.D26 IC2.B1 IC5.N5 R12.2 | length 21.1
  Top w0.4: v2(31.25,-1.2) IC5.N5@31.65,-1.6
  L4 w0.1: v1(36.5,-8.81) 36.541,-8.851 v1(36.541,-10.26) 37.131,-10.26 42.396,-4.995 v3(42.396,-4.535)
  Bottom w0.2: v2(31.25,-1.2) 31.264,-1.2 34.675,-4.611 34.675,-6.985 v1(36.5,-8.81)
  Bottom w0.3: v1(36.541,-10.26) 36.805,-9.996 IC2.B1@37.249,-9.996
LMS_MCLK1: IC1.AB34 IC5.G5 | length 15.4
  Top w0.15: v1@36.025,1.068 36.038,1.08 36.416,1.459 IC1.AB34@39.732,1.459
  Top w0.4: v2(26.45,-1.2) IC5.G5@26.85,-1.6
  L6 w0.1: v2(26.45,-1.2) 26.9,-0.75 29.86,-0.75 30.075,-0.535 30.075,-0.125 30.25,0.05 31.317,0.05 31.502,-0.135 34.075,-0.135 34.5,0.29 35.272,0.29 v1(36.05,1.068)
LMS_MCLK2: IC1.P34 IC5.H4 | length 14.6
  Top w0.15: v1(35.8,-2.182) 37.578,-2.182 38.555,-1.205 IC1.P34@39.732,-1.205
  Top w0.4: v2(27.25,-2) IC5.H4@27.65,-2.4
  L6 w0.1: v2(27.25,-2) 27.66,-2.41 33.775,-2.41 34.425,-1.76 34.425,-1.56 34.575,-1.41 35.24,-1.41 35.8,-1.97 v1(35.8,-2.182)
LMS_RESET: IC1.E27 IC5.L1 R2.1 | length 14.6
  Top w0.4: v2(29.65,-4.4) IC5.L1@30.05,-4.8 R2.1@30.05,-6.035
  L4 w0.1: v2(29.65,-4.4) 30.01,-4.76 40.325,-4.76 40.75,-4.335 41.425,-4.335 41.55,-4.21 42.055,-4.21 v3(42.063,-4.202)
LMS_RXEN: IC1.V34 IC5.M11 R4.2 | length 16.1
  Top w0.15: v1@36.5,-0.132 37.753,-0.132 38.076,0.191 39.732,0.191 IC1.V34@39.732,0.127
  Top w0.4: v2(30.45,3.6) IC5.M11@30.85,3.2
  L4 w0.1: v2(30.45,3.6) 30.8,3.25 30.8,2.655 30.595,2.45 30.405,2.45 30.075,2.12 30.075,1.08 30.365,0.79 31.358,0.79 32.305,-0.157 v1(36.5,-0.157)
  Bottom w0.2: R4.2@34.625,-0.66 35.053,-0.232 36.425,-0.232 v1(36.5,-0.157)
LMS_TXEN: IC1.U29 IC5.K6 R3.2 | length 18.2
  Top w0.4: v2(28.85,-0.4) IC5.K6@29.25,-0.8
  L5 w0.1: v2(28.85,-0.4) 29.2,-0.05 31.84,-0.05 32.025,-0.235 35.95,-0.235 36.479,-0.764 40.346,-0.764 40.563,-0.547 41.056,-0.547 v3(41.397,-0.206)
  Bottom w0.11: R3.2@37.8,-2.11 37.85,-2.11 39.418,-0.542 41.061,-0.542 v3(41.397,-0.206)
LMS_TXNRX1: IC1.V32 IC5.J8 R1.1 | length 19.1
  Top w0.4: v2(28.05,1.2) IC5.J8@28.45,0.8
  L4 w0.1: v2(28.05,1.2) 28.45,0.8 28.45,0.265 28.75,-0.035 31.55,-0.035 31.872,-0.357 36.197,-0.357 36.347,-0.507 38.228,-0.507 38.862,0.127 v3(40.398,0.127)
  Bottom w0.15: R1.1@36.3,2.14 36.325,2.115 37.504,2.115 39.509,0.11 40.381,0.11 v3(40.398,0.127)
LMS_TXNRX2: IC1.U31 IC5.H5 R10.1 | length 21.7
  Top w0.4: v2(27.25,-1.2) IC5.H5@27.65,-1.6
  L4 w0.1: v2(27.25,-1.2) 27.533,-1.2 27.883,-0.85 35.14,-0.85 35.375,-1.085 38.8,-1.085 39.679,-0.206 v3(40.731,-0.206)
  Bottom w0.15: R10.1@34.425,1.365 34.535,1.475 37.79,1.475 39.488,-0.223 40.714,-0.223 v3(40.731,-0.206)
NetC1_1: C1.1 IC1.C29 R6.1 | length 3.4
  Bottom w0.2: R6.1@40.251,-7.814 40.251,-7.739 41.397,-6.593 v3(41.397,-4.868)
NetC11_2: C11.2 C12.1 MN23.2 R14.2 R15.2
  other v1: 63.675,-9.66 64.225,-9.66
NetC13_1: C13.1 IC3.6 | length 1.6
  Top w0.309: IC3.6@58.975,-5.51 C13.1@58.975,-3.935
NetC14_1: C14.1 IC3.3 | length 1.7
  Top w0.309: IC3.3@60.025,-6.86 60.695,-6.86 ccw(c60.695,-5.58) C14.1@61.6,-6.485
NetC15_1: C15.1 IC3.1 | length 1.7
  Top w0.309: C15.1@58.975,-8.485 IC3.1@58.975,-6.76
NetC16_1: C16.1 IC3.4 | length 2.3
  Top w0.309: IC3.4@60.025,-5.41 60.75,-5.41 ccw(c60.75,-4.41) C16.1@61.75,-4.41
NetC16_2: C16.2 R18.1 R19.1 R23.2 VT1.1 VT3.2 | length 7
  Top w0.309: C16.2@61.75,-3.31 v1(61.75,-2.785)
  Bottom w0.309: v1(61.75,-2.785) 61.75,-0.056 cw(c62.646,-0.056) R19.1@62.012,0.577 62.012,2.16 ccw(c61.97,2.16) VT1.1@62,2.19 62.6,2.79 cw(c63.112,2.278) R18.1@63.112,3.002
NetC21_2: C21.2 C22.1 MN24.2 R20.2 R21.2 | length 3.1
  Bottom w0.4: C22.1@64.225,8.865 64.225,10.802 64.7,11.277 C21.2@64.7,11.765
  other v1: 64.225,9.715 64.225,10.19
NetC24_1: C24.1 IC4.6 | length 3.5
  Top w0.309: C24.1@56.525,11.365 58.45,11.365 ; 58.4,11.365 cw(c58.4,10.415) IC4.6@59.35,10.415 IC4.6@59.35,10.315
NetC25_1: C25.1 IC4.3 | length 1.7
  Top w0.309: IC4.3@60.425,8.965 60.758,8.965 cw(c60.758,7.173) C25.1@62.025,8.44
NetC26_1: C26.1 IC4.1 | length 2.2
  Top w0.309: IC4.1@59.35,9.065 IC4.1@59.35,8.965 59.35,7.156 ccw(c59.691,7.156) C26.1@59.45,6.915
NetC27_1: C27.1 IC4.4 | length 2.1
  Top w0.309: IC4.4@60.35,10.415 60.35,10.315 cw(c61.255,10.315) 60.615,10.955 60.975,11.315 cw(c61.639,10.651) 61.639,11.59 C27.1@61.7,11.59
NetC27_2: C27.2 R16.1 R18.2 R24.2 VT2.2 | length 8.2
  Top w0.309: C27.2@62.75,11.59 v1(63.275,11.59)
  Bottom w0.309: R18.2@63.162,4.052 ccw(c62.74,4.475) 63.337,4.475 R24.2@63.337,6.252 ; VT2.2@63.25,10.69 cw(c63.069,10.509) VT2.2@63.275,10.661 ; v1(63.275,11.59) VT2.2@63.275,10.661 ; R24.2@63.325,6.215 63.325,10.509 ccw(c63.069,10.509) VT2.2@63.275,10.661
NetC30_1: C30.1 IC1.D24 R26.1 | length 2.7
  Bottom w0.22: R26.1@42.631,-7.054 C30.1@42.631,-6.539 ; C30.1@42.681,-6.539 42.681,-5.559 43.114,-5.126 43.114,-4.587 v3(43.062,-4.535)
NetC31_1: C31.1 C32.1 IC1.W31 R31.2 | length 2.6
  Bottom w0.2: R31.2@42.001,-0.164 42.076,-0.089 C32.1@42.696,-0.089
  Bottom w0.25: C31.1@41.099,0.763 41.099,0.658 41.575,0.181 41.681,0.181 42.001,-0.139 R31.2@42.001,-0.164
  Bottom w0.3: v3(40.731,0.46) 40.796,0.46 C31.1@41.099,0.763
NetC33_1: C33.1 C34.1 IC1.H32 R30.2 | length 3.2
  Bottom w0.35: R30.2@38.301,-4.414 39.835,-4.414 40.206,-4.043 40.206,-3.395 40.357,-3.244 C34.1@40.05,-3.244
  other v6: 40.398,-3.203
NetC35_1: C35.1 C36.1 IC1.T32 R29.2 | length 3.7
  Top w0.11: v1(38.951,-0.414) 39.073,-0.536 IC1.T32@40.395,-0.536
  Bottom w0.25: C36.1@37.696,-0.159 C36.1@37.747,-0.21 ; R29.2@37.801,-1.014 37.801,-0.264 C36.1@37.747,-0.21 ; v1(38.951,-0.414) 38.747,-0.21 C35.1@38.325,-0.21 C36.1@37.747,-0.21
NetC37_1: C37.1 C38.1 IC1.W33 R28.2 | length 3.2
  Bottom w0.3: R28.2@38.422,2.59 38.422,1.656 38.938,1.14 39.142,1.14 C38.1@39.146,1.136 39.426,0.856 C37.1@39.926,0.856 39.926,0.599 v3(40.065,0.46)
NetC39_1: C39.1 C40.1 IC1.AH30 R27.2 | length 2.6
  Bottom w0.3: R27.2@38.601,3.686 40.835,3.686 v3(41.064,3.457)
NetC41_1: C41.1 FR1.1 IC1.G3 | length 2.1
  Bottom w0.3: v3(50.055,-3.536) 50.055,-3.551 50.837,-4.334 FR1.1@51.851,-4.334
NetC42_1: C42.1 FR8.1 IC1.E21 | length 7.6
  Bottom w0.11: v3(44.061,-4.202) 44.73,-4.871 45.863,-4.871 46.08,-5.088 C42.1@46.08,-6.11
  Bottom w0.3: C42.1@46.08,-6.11 46.08,-7.441 46.444,-7.805 46.816,-7.805 47.175,-7.446 FR8.1@47.175,-5.965
NetC43_1: C43.1 FR7.1 IC1.D16 | length 1.3
  Bottom w0.35: v3(45.725,-4.532) 46.603,-4.532 C43.1@46.603,-4.953
NetC44_1: C44.1 FR6.1 IC1.E17 | length 1.2
  Bottom w0.35: v3(45.393,-4.202) 45.995,-3.6 C44.1@45.995,-3.285
NetC45_1: C45.1 FR5.1 IC1.AK22 | length 6.8
  L3 w0.35: v1(38.675,6.14) 39.65,6.14 42.5,3.29 43.225,3.29 43.728,3.793 v3(43.728,4.123)
NetC46_1: C46.1 FR4.1 IC1.AM18 | length 1.8
  Bottom w0.31: v3(45.06,4.789) 45.163,4.686 45.576,4.686 45.826,4.936 FR4.1@45.826,5.831
NetC47_1: C47.1 FR3.2 IC1.AE3 IC1.AF4 | length 1.9
  Top w0.3: IC1.AF4@49.722,2.791 v3(50.055,2.458)
  Bottom w0.3: v3(50.055,2.458) 50.148,2.365 50.67,2.365 C47.1@50.82,2.215 FR3.2@50.82,1.69
NetC48_1: C48.1 FR2.2 IC1.N1 | length 1.1
  Bottom w0.3: C48.1@50.771,-2.114 50.721,-2.064 v3(50.721,-1.538) 50.883,-1.376 FR2.2@51.144,-1.376
NetC49_1: C49.1 FR10.1 IC1.AM26 | length 1.4
  Bottom w0.3: C49.1@41.101,5.156 FR10.1@41.876,5.156 42.029,5.156 v3(42.396,4.789)
NetC50_1: C50.1 FR9.2 IC1.H6 | length 3.7
  Bottom w0.11: v3(49.056,-3.203) 50.346,-3.203
  Bottom w0.2: 50.346,-3.207 C50.1@52.017,-3.207 ; FR9.2@52.017,-3.757 52.021,-3.753 C50.1@52.021,-3.039
NetC51_1: C51.1 FR10.2 R33.2 | length 2.5
  Bottom w0.4: R33.2@39.801,6.531 39.801,6.336 40.371,5.766 FR10.2@41.901,5.766
NetC52_1: C52.1 FR9.1 R32.1 | length 1.4
  Bottom w0.4: FR9.1@52.585,-3.757 52.738,-3.911 R32.1@53.054,-3.911 ; R32.1@53.129,-3.911 53.937,-3.911 C52.1@53.944,-3.903
NetC53_1: C53.1 C54.1 C64.1 C65.1 IC1.AA29 IC1.AE29 | length 4.4
  L4 w0.35: v3(41.397,1.126) 41.847,1.576 41.847,1.978 41.397,2.428 v3(41.397,2.458)
  Bottom w0.3: v3(41.397,1.126) 42.666,1.126 C65.1@42.676,1.116 ; v3(41.397,2.458) 41.639,2.216 C54.1@42.676,2.216
NetC55_1: C55.1 IC1.A17 | length 0.5
  Bottom w0.35: C55.1@44.879,-5.534 v3(45.393,-5.534)
NetC56_1: C56.1 IC1.F24 | length 0.8
  Bottom w0.3: C56.1@42.456,-3.414 42.542,-3.414 42.997,-3.869 v3(43.062,-3.869)
NetC57_1: C57.1 IC1.C25 | length 0.6
  Bottom w0.25: C57.1@42.351,-5.334 42.729,-4.956 v3(42.729,-4.868)
NetC58_2: C58.2 IC1.M4 | length 2.1
  Bottom w0.35: v3(49.722,-1.871) 50.275,-1.318 50.275,-0.96 50.525,-0.71 C58.2@51.125,-0.71
  other v3: 50.6,-0.71
NetC59_1: C59.1 IC1.AL21 | length 1.7
  Bottom w0.35: v3(44.061,4.456) 44.501,4.016 44.501,3.664 44.672,3.493 C59.1@45.125,3.493
NetC60_1: C60.1 C61.1 C62.1 C63.1 IC1.L33 IC1.R31 | length 6.8
  Top w0.2: v1(39.1,-2.632) 39.1,-2.557 39.495,-2.162 40.065,-2.162 IC1.L33@40.065,-2.204
  Bottom w0.22: 39.851,-1.039 40.08,-0.81 40.669,-0.81 v3(40.731,-0.872)
  Bottom w0.3: C60.1@37.875,-3.032 C60.1@37.875,-3.032 C61.1@38.926,-3.034 38.926,-2.806 v1(39.1,-2.632)
  Bottom w0.37: v1(39.1,-2.632) 38.887,-2.632 38.625,-2.37 38.625,-1.86 38.894,-1.591 C63.1@39.851,-1.591 39.851,-1.039
NetC66_1: C66.1 IC1.P4 | length 0.7
  Bottom w0.35: C66.1@49.2,-1.66 49.267,-1.66 v3(49.722,-1.205)
NetC67_1: C67.1 IC1.D6 IC1.F8 | length 1.6
  Bottom w0.25: v3(48.39,-3.869) v3(49.056,-4.535) 49.474,-4.953 C67.1@49.474,-4.985
NetC68_1: C68.1 IC1.B16 | length 1.6
  Bottom w0.2: C68.1@44.35,-5.33 44.554,-5.126 45.651,-5.126 v3(45.726,-5.201) v3@45.768,-5.243
NetC69_1: C69.1 IC1.E19 | length 0.8
  Bottom w0.11: v3(44.727,-4.202) C69.1@44.727,-3.389
NetC70_2: C70.2 IC1.F20 | length 0.5
  Bottom w0.35: C70.2@43.9,-3.735 44.26,-3.735 v3(44.394,-3.869)
NetC71_1: C71.1 IC1.AJ25 | length 0.6
  Bottom w0.35: v3@42.722,3.79 v3(42.729,3.79) 42.958,3.561 C71.1@43.233,3.561
NetC72_1: C72.1 IC1.AP26 | length 1.7
  Bottom w0.3: C72.1@41.326,6.256 42.101,6.256 42.396,5.961 v3(42.396,5.455)
NetC73_1: C73.1 IC1.AN23 | length 1
  Bottom w0.3: C73.1@43.176,6.056 43.176,5.341 v3(43.395,5.122)
NetC74_1: C74.1 IC1.AM20 | length 0.4
  Bottom w0.35: v3(44.394,4.789) 44.394,5.216 C74.1@44.396,5.218
NetC75_1: C75.1 IC1.AL19 | length 1.2
  Bottom w0.11: v3(44.727,4.456) 44.726,5.061
  Bottom w0.3: 44.871,5.406 44.931,5.466 C75.1@44.931,5.986
NetC76_1: C76.1 IC1.AG5 | length 0.4
  Bottom w0.35: v3(49.389,3.124) C76.1@49.389,3.51
NetC77_2: C77.2 IC1.AD6 | length 0.5
  Bottom w0.35: v3(49.056,2.125) 49.15,2.031 C77.2@49.15,1.695
NetC78_1: C78.1 IC1.J3 | length 2.2
  Bottom w0.19: v3(50.055,-2.87) 50.092,-2.907 51.403,-2.907 51.796,-2.514 52.006,-2.514 C78.1@52.05,-2.557
NetC79_2: C79.2 IC1.J5 IC1.K6 | length 1.3
  Top w0.2: v3(49.056,-2.537) IC1.J5@49.389,-2.87
  Bottom w0.35: C79.2@48.475,-3.085 48.508,-3.085 v3(49.056,-2.537)
NetC80_1: C80.1 IC1.G5 | length 0.6
  Bottom w0.2: C80.1@49.769,-3.95 C80.1@49.803,-3.95
  Bottom w0.3: v3(49.389,-3.536) C80.1@49.803,-3.95
NetC81_1: C81.1 IC1.K2 IC1.L5 | length 2.2
  Bottom w0.3: C81.1@48.431,-2.289 48.608,-2.112 49.297,-2.112 49.63,-2.445 50.296,-2.445 v3(50.388,-2.537)
  other v3: 49.389,-2.204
